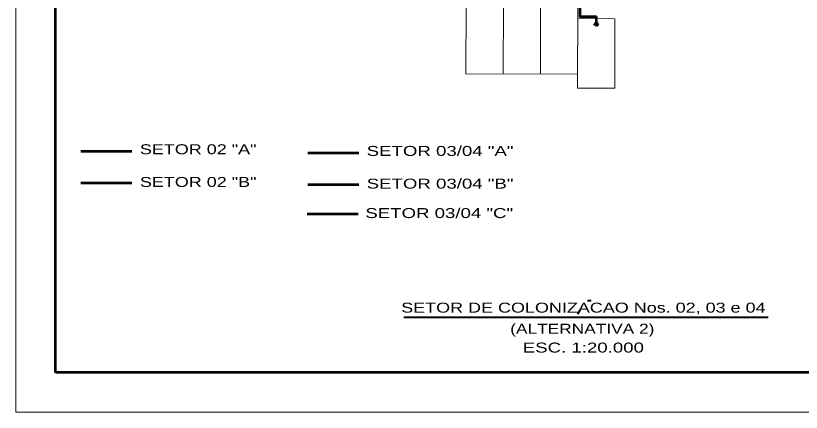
# Model space of a CAD drawing. Extents: x 312964 to 351929, y 9004151 to 9034973.
# Drawn here: x 342096 to 346044, y 9026573 to 9028567 of the extents above; entities that cross this region are included whole.
import ezdxf
from ezdxf.enums import TextEntityAlignment as Align

# ---------------------------------------------------------------- set-up
doc = ezdxf.new("R2010")
doc.units = 0
doc.header["$LTSCALE"] = 10
doc.layers.add('1', color=7, linetype='Continuous', lineweight=13)
doc.layers.add('2', color=7, linetype='Continuous', lineweight=53)

msp = doc.modelspace()

# ---------------------------------------------------------------- linework, layer by layer
at = {"layer": '1', "lineweight": 53}
for p, q in [((342296.46, 9026772.79), (342296.46, 9034472.79)), ((342423.79, 9027886.2), (342679.74, 9027886.2)), ((343565.24, 9027877.74), (343821.19, 9027877.74)), ((342423.79, 9027727.19), (342679.74, 9027727.19)), ((343565.24, 9027718.73), (343821.19, 9027718.73)), ((347836.46, 9026772.79), (342296.46, 9026772.79))]:
    msp.add_line(p, q, dxfattribs=at)
at = {"layer": '1'}
for p, q in [((344360.24, 9028624.93), (344358.91, 9028274.93)), ((344547.24, 9028624.22), (344545.91, 9028274.22)), ((344734.24, 9028623.51), (344732.91, 9028273.52)), ((344921.23, 9028622.81), (344919.64, 9028202.81)), ((344920.97, 9028552.81), (345107.97, 9028552.1)), ((345107.97, 9028552.1), (345106.64, 9028202.1)), ((344358.91, 9028274.93), (344919.91, 9028272.81)), ((344919.64, 9028202.81), (345106.64, 9028202.1))]:
    msp.add_line(p, q, dxfattribs=at)
at = {"layer": '1', "lineweight": 40}
for p, q in [((344969.77, 9027135.18), (344988.06, 9027135.18)), ((344931.79, 9027085.34), (344919.13, 9027065.63)), ((344046.75, 9027051.27), (345878.08, 9027051.27))]:
    msp.add_line(p, q, dxfattribs=at)
at = {"layer": '1'}
msp.add_lwpolyline([(348036.46, 9030772.79), (348036.46, 9026572.79), (342096.46, 9026572.79), (342096.46, 9030772.79)], dxfattribs=at)
at = {"layer": '2'}
for p, q in [((345014.36, 9028526.6), (345014.48, 9028562.45)), ((345003.84, 9028526.64), (345025.4, 9028526.57)), ((345014.58, 9028515.82), (345003.84, 9028526.64)), ((345014.58, 9028515.82), (345025.4, 9028526.57)), ((343561.01, 9027570.65), (343816.96, 9027570.65))]:
    msp.add_line(p, q, dxfattribs=at)
msp.add_lwpolyline([(344312.5, 9028635.11), (344672.49, 9028633.75), (344931.27, 9028632.77), (344931.01, 9028562.77), (345014.51, 9028562.45)], dxfattribs=at)

# ---------------------------------------------------------------- texts
at = {"layer": '1'}
for s, width, p in [('SETOR 02 "A"', 1.35, (343013.34, 9027870.69)), ('SETOR 03/04 "A"', 1.4, (344229.01, 9027862.23)), ('SETOR 02 "B"', 1.35, (343013.34, 9027706.2)), ('SETOR 03/04 "B"', 1.4, (344229.01, 9027697.74)), ('SETOR 03/04 "C"', 1.4, (344224.78, 9027549.65)), ('SETOR DE COLONIZACAO Nos. 02, 03 e 04', 1.35, (344949.14, 9027074.14)), ('(ALTERNATIVA 2)', 1.3, (344943.7, 9026968.03)), ('ESC. 1:20.000', 1.4, (344948.96, 9026873.39))]:
    msp.add_text(s, height=50, dxfattribs=dict(at, width=width)).set_placement(p, align=Align.CENTER)

doc.saveas('drawing.dxf')
